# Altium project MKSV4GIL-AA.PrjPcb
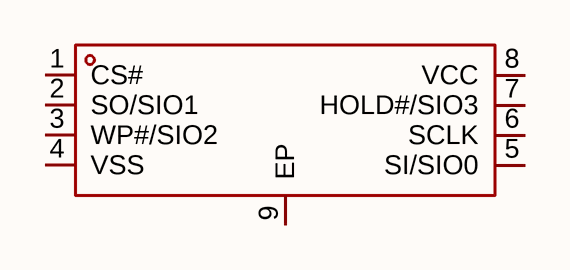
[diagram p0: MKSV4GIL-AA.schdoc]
1 sheet, 1 parts. Net scope: global (net labels, ports and power ports of the same name join across sheets).

## Sheet MKSV4GIL-AA.schdoc
size 127 x 101 mm

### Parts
U?  mksv4gil-aa  [LGA-8_L8.0-W6.0-P1.27-TL-EP]  (value not drawn)

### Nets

Not connected (* = marked no-connect by the designer): U? 1(CS#) 2(SO/SIO1) 3(WP#/SIO2) 4(VSS) 5(SI/SIO0) 6(SCLK) 7(HOLD#/SIO3) 8(VCC) 9(EP)

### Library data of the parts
U? = mksv4gil-aa: 存储容量:4Gbit;时钟频率(fc):104MHz;工作电压:2.7V~3.6V;; Manufacturer: MK(米客方德); AddInBom: yes; ModelId: 173079a3dc6c426c9373cb3e9b56ed68; ModelTransform: 314.96,236.22,0,0,0,0,0,0,0; Memory Size: 4Gbit; Interface: SPI; Clock Frequency: 104MHz; Page Program time (TPP): 490us; Block Erase Time(tBE): 2ms; Standby Supply Current: 100uA; ECC: 有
